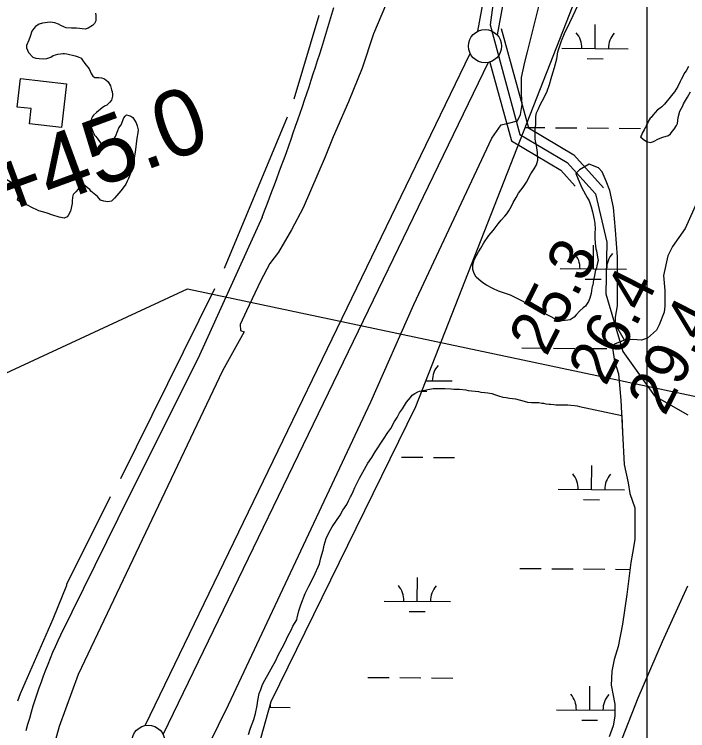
# Model space of a CAD drawing. Extents: x 3271442 to 3309282, y 752266 to 777610.
# Drawn here: x 3285122 to 3286138, y 766109 to 767190 of the extents above; entities that cross this region are included whole.
import ezdxf

# ---------------------------------------------------------------- set-up
doc = ezdxf.new("R2010")
doc.units = 0
for name, color, linetype in [('V-BLDG-OTLN', 7, 'Continuous'), ('V-GRID-MAJR', 7, 'Continuous'), ('V-LEVE-TOET', 7, 'Continuous'), ('V-RIVR-RANG', 7, 'Continuous'), ('V-ROAD-CNTR', 7, 'Continuous'), ('V-SITE-VEGE', 7, 'Continuous'), ('V-SURV-IDEN', 7, 'Continuous'), ('V-SURV-LINE', 7, 'Continuous'), ('V-TOPO-MINR', 7, 'Continuous'), ('V-TOPO-SHOR', 7, 'Continuous'), ('V-UTIL-LINE', 7, 'Continuous'), ('V-WETL-SWMP', 7, 'Continuous')]:
    doc.layers.add(name, color=color, linetype=linetype)

msp = doc.modelspace()

# ---------------------------------------------------------------- linework, layer by layer
at = {"layer": 'V-BLDG-OTLN'}
msp.add_lwpolyline([(3285145, 767024.6), (3285147.7, 767047.6), (3285126.6, 767050), (3285131.6, 767093.1), (3285200.8, 767085.1), (3285193.2, 767019)], close=True, dxfattribs=at)
at = {"layer": 'V-GRID-MAJR'}
msp.add_spline([(3286078, 757644.7), (3286077.1, 763703.6), (3286076.2, 769765.5), (3286075.4, 775827.4), (3286075.4, 775830.5)], degree=3, dxfattribs=at)
at = {"layer": 'V-LEVE-TOET'}
for points in [[(3285399.7, 766055.2), (3285445, 766148.2), (3285660, 766605.4), (3285724.8, 766752.3), (3285842.3, 767003), (3285856.6, 767022.9), (3285867.4, 767025.7), (3285881.1, 767029), (3285885.6, 767038.7), (3285888, 767054), (3285886.9, 767069.9), (3285887, 767094.4), (3285892.2, 767117.6), (3285896.3, 767133.5), (3285919.4, 767226.1), (3286015.1, 767705.3), (3286090.6, 768109.6), (3286175.4, 768562.2), (3286231.2, 768857.5), (3286256.7, 768984.7), (3286280.4, 769073.9), (3286345.1, 769332.2)], [(3285696.1, 767236.6), (3285663.9, 767160.6), (3285646.7, 767108.4), (3285626, 767057.9), (3285603.1, 767005.2), (3285591, 766975.1), (3285557.7, 766897.9), (3285540, 766864.5), (3285520.5, 766831), (3285507.4, 766814), (3285493.6, 766787.4), (3285472.4, 766742.6), (3285462.7, 766722.1), (3285463.2, 766713.1), (3285468.9, 766710.8), (3285436.2, 766651.8), (3285218.4, 766194.1), (3285189.7, 766115.7), (3285173.5, 766055.6)]]:
    msp.add_lwpolyline(points, dxfattribs=at)
at = {"layer": 'V-ROAD-CNTR'}
for points in [[(3285692, 767487.4), (3285764.1, 767481.4), (3285854.2, 767284.3), (3285839.6, 767174.2), (3285884.7, 767008.7), (3285956.1, 766966.3), (3285998.6, 766919), (3286015.9, 766846.1), (3286014.2, 766768.2), (3286039.7, 766681.3), (3286087.8, 766614.1), (3286138, 766585.7)], [(3285856.6, 767168.7), (3285897.6, 767018.5), (3285965.8, 766978.1), (3286010.7, 766927.9)], [(3285839, 767119.2), (3285871.8, 766998.8), (3285946.5, 766954.6), (3285968.2, 766930.5)], [(3285495.8, 766883.7), (3285401.4, 766675.5), (3285278.5, 766428.7), (3285191.7, 766253.2)]]:
    msp.add_lwpolyline(points, dxfattribs=at)
for centre, radius, start, end in [((3281662.7, 768375), 4113, 338.7423, 343.4002), ((3285957.6, 765895.8), 845.1, 154.9809, 165.3761)]:
    msp.add_arc(centre, radius, start, end, dxfattribs=at)
at = {"layer": 'V-SITE-VEGE'}
for p, q in [((3285730.5, 766620.1), (3285733.4, 766621.1)), ((3285733.4, 766621.1), (3285741.2, 766623)), ((3285741.2, 766623), (3285745.6, 766624)), ((3285745.6, 766624), (3285753.9, 766625.4)), ((3285753.9, 766625.4), (3285771.4, 766625.3)), ((3285771.4, 766625.3), (3285781.1, 766624.8)), ((3285781.1, 766624.8), (3285785, 766624.3)), ((3285785, 766624.3), (3285785.7, 766624.3)), ((3285785.7, 766624.3), (3285793.8, 766624.3)), ((3285793.8, 766624.3), (3285803.1, 766623.2)), ((3285803.1, 766623.2), (3285806.5, 766622.2)), ((3285806.5, 766622.2), (3285822, 766620.7)), ((3285822, 766620.7), (3285825.9, 766619.7)), ((3285713.8, 766604.6), (3285719.7, 766611.9)), ((3285719.7, 766611.9), (3285722.2, 766615.3)), ((3285722.2, 766615.3), (3285726.1, 766617.7)), ((3285726.1, 766617.7), (3285730.5, 766620.1)), ((3285825.9, 766619.7), (3285831.8, 766619.2)), ((3285831.8, 766619.2), (3285836.2, 766618.7)), ((3285836.2, 766618.7), (3285842.5, 766617.7)), ((3285842.5, 766617.7), (3285846.4, 766616.2)), ((3285846.4, 766616.2), (3285852.2, 766614.3)), ((3285852.2, 766614.3), (3285859, 766612.3)), ((3285859, 766612.3), (3285863.9, 766611.8)), ((3285863.9, 766611.8), (3285868.8, 766610.8)), ((3285868.8, 766610.8), (3285878, 766609.8)), ((3285878, 766609.8), (3285891.2, 766606.3)), ((3285707.5, 766594.9), (3285713.8, 766604.6)), ((3285891.2, 766606.3), (3285896, 766604.8)), ((3285896, 766604.8), (3285901.9, 766604.3)), ((3285901.9, 766604.3), (3285913.1, 766604.3)), ((3285913.1, 766604.3), (3285917.5, 766603.3)), ((3285917.5, 766603.3), (3285920.4, 766603.3)), ((3285920.4, 766603.3), (3285923.8, 766602.3)), ((3285923.8, 766602.3), (3285928.7, 766601.8)), ((3285928.7, 766601.8), (3285931.1, 766601.8)), ((3285931.1, 766601.8), (3285936, 766601.3)), ((3285936, 766601.3), (3285938.9, 766600.8)), ((3285938.9, 766600.8), (3285949.6, 766600.7)), ((3285949.6, 766600.7), (3285956.9, 766600.7)), ((3285956.9, 766600.7), (3285961.3, 766600.2)), ((3285961.3, 766600.2), (3285967.1, 766599.7)), ((3285967.1, 766599.7), (3285971, 766599.2)), ((3285971, 766599.2), (3285974.4, 766598.2)), ((3285699.6, 766581.8), (3285703, 766588.6)), ((3285703, 766588.6), (3285707.5, 766594.9)), ((3285974.4, 766598.2), (3286038.2, 766584.6)), ((3285695.7, 766575.4), (3285699.6, 766581.8)), ((3286038.2, 766584.6), (3286039.6, 766559.1)), ((3285689.8, 766564.8), (3285695.7, 766575.4)), ((3285679, 766548.7), (3285685.4, 766558.9)), ((3285685.4, 766558.9), (3285689.8, 766564.8)), ((3286039.6, 766559.1), (3286041.7, 766510.7)), ((3285666.3, 766529.8), (3285679, 766548.7)), ((3285661.4, 766521.5), (3285666.3, 766529.8)), ((3285642.7, 766489.9), (3285655.5, 766512.8)), ((3285655.5, 766512.8), (3285661.4, 766521.5)), ((3286041.7, 766510.7), (3286047.8, 766482.9)), ((3285635.8, 766475.8), (3285642.7, 766489.9)), ((3286047.8, 766482.9), (3286050.6, 766466.9)), ((3285630.4, 766463.7), (3285633.4, 766470)), ((3285633.4, 766470), (3285635.8, 766475.8)), ((3285626, 766455.9), (3285629.4, 766461.7)), ((3285629.4, 766461.7), (3285630.4, 766463.7)), ((3286050.6, 766466.9), (3286057.9, 766445.3)), ((3285617.7, 766441.8), (3285623.6, 766450.5)), ((3285623.6, 766450.5), (3285626, 766455.9)), ((3285613.7, 766434.5), (3285617.7, 766441.8)), ((3286057.9, 766445.3), (3286058.2, 766397.6)), ((3285601.5, 766416.5), (3285613.7, 766434.5)), ((3285597.1, 766408.8), (3285601.5, 766416.5)), ((3285592.7, 766399), (3285597.1, 766408.8)), ((3285589.7, 766388.8), (3285592.7, 766399)), ((3286058.2, 766397.6), (3286054.2, 766377.1)), ((3285588.2, 766381.5), (3285589.7, 766388.8)), ((3285584.7, 766369.8), (3285588.2, 766381.5)), ((3286054.2, 766377.1), (3286051.9, 766362.9)), ((3285573.9, 766341.6), (3285582.3, 766361.1)), ((3285582.3, 766361.1), (3285584.7, 766369.8)), ((3286051.9, 766362.9), (3286046, 766314.7)), ((3285566.5, 766327), (3285573.9, 766341.6)), ((3285560.7, 766315.9), (3285566.5, 766327)), ((3285554.2, 766298.8), (3285560.7, 766315.9)), ((3286046, 766314.7), (3286039.5, 766269.8)), ((3285551.3, 766290.1), (3285554.2, 766298.8)), ((3285548.8, 766279.4), (3285551.3, 766290.1)), ((3285544.9, 766271.1), (3285548.3, 766276.4)), ((3285548.3, 766276.4), (3285548.8, 766279.4)), ((3285539.5, 766260.9), (3285542.4, 766266.7)), ((3285542.4, 766266.7), (3285544.9, 766271.1)), ((3286039.5, 766269.8), (3286032.6, 766236.3)), ((3285535.1, 766252.6), (3285539.5, 766260.9)), ((3285530.1, 766241.9), (3285535.1, 766252.6)), ((3285520.3, 766223), (3285526.2, 766234.1)), ((3285526.2, 766234.1), (3285530.1, 766241.9)), ((3286032.6, 766236.3), (3286026.8, 766216.4)), ((3285516.4, 766215.2), (3285520.3, 766223)), ((3285500.2, 766185.5), (3285516.4, 766215.2)), ((3286026.8, 766216.4), (3286023.3, 766198.8)), ((3286023.3, 766198.8), (3286022.1, 766177.8)), ((3285493.8, 766171.4), (3285496.3, 766178.7)), ((3285496.3, 766178.7), (3285500.2, 766185.5)), ((3286022.1, 766177.8), (3286027.7, 766149.4)), ((3285491.3, 766165.1), (3285493.8, 766171.4)), ((3285489.4, 766154.9), (3285491.3, 766165.1)), ((3285485.9, 766134.9), (3285488.4, 766147.1)), ((3285488.4, 766147.1), (3285489.4, 766154.9)), ((3286027.7, 766149.4), (3286027.6, 766131.2)), ((3285483.4, 766126.2), (3285485.9, 766134.9)), ((3285478.5, 766113), (3285483.4, 766126.2)), ((3286027.6, 766131.2), (3286025.3, 766116.4)), ((3285475.5, 766103.3), (3285478.5, 766113)), ((3286025.3, 766116.4), (3286019.5, 766100))]:
    msp.add_line(p, q, dxfattribs=at)
for points in [[(3285947.4, 767149.9), (3285951.8, 767161.1), (3285960.1, 767177.6), (3285965.1, 767187.9), (3285971.5, 767202.4), (3285974.4, 767212.2), (3285977.9, 767222.4), (3286003.1, 767285.8), (3286025.9, 767399.8), (3286045.8, 767499.5), (3286099.9, 767747.4), (3286114.2, 767912.6), (3286140.1, 768054.3)], [(3285244.6, 767191.6), (3285245.1, 767188.2), (3285245.1, 767179.9), (3285243.1, 767176), (3285240.2, 767173.1), (3285233.8, 767168.8), (3285229, 767167.3), (3285215.8, 767168.8), (3285208.5, 767168.9), (3285200.7, 767169.4), (3285197.8, 767170.4), (3285192.4, 767172.8), (3285189, 767174.8), (3285183.2, 767177.2), (3285179.8, 767177.7), (3285176.4, 767177.8), (3285164.7, 767176.3), (3285159.8, 767174.9), (3285157.4, 767173.5), (3285154.4, 767171.5), (3285151.5, 767168.6), (3285148.6, 767164.2), (3285146.1, 767156.4), (3285144.1, 767151.1)], [(3285144.1, 767151.1), (3285140.7, 767142.8), (3285140.7, 767139.4), (3285143.6, 767132.1), (3285150.3, 767125.2), (3285154.7, 767123.8), (3285159.6, 767123.3), (3285166.9, 767122.7), (3285171.3, 767123.2), (3285177.1, 767125.1), (3285181, 767127.6), (3285187.9, 767129.5), (3285191.8, 767130.4), (3285195.2, 767130.9), (3285198.1, 767130.9), (3285201.5, 767130.4), (3285214.2, 767127.4), (3285218.6, 767125.9), (3285222.9, 767123.5), (3285224.9, 767120.6), (3285228.7, 767115.7), (3285235, 767107.4), (3285238.4, 767100.5), (3285240.8, 767096.6), (3285243.8, 767094.7), (3285249.6, 767094.6), (3285253.5, 767094.1), (3285257.4, 767093.1), (3285260.3, 767091.2), (3285263.7, 767087.8), (3285267.1, 767081.9), (3285269, 767076), (3285270, 767073.6), (3285270.4, 767068.7), (3285270.4, 767066.3), (3285269, 767060.5), (3285266.5, 767057.1), (3285261.6, 767052.7), (3285258.2, 767051.2), (3285254.8, 767048.8), (3285246, 767041.6), (3285241.6, 767037.7), (3285240.1, 767035.7), (3285238.6, 767032.8), (3285238.1, 767030.4), (3285238.1, 767020.2), (3285240.5, 767013.3), (3285242, 767009.9), (3285243.4, 767007.5)], [(3286003.1, 766958.1), (3285988.9, 766963.8), (3285974.6, 766955.3), (3285968.9, 766949.6), (3285977.6, 766929.1), (3285983.4, 766918.2), (3285985.9, 766913.5), (3285989.2, 766908.6), (3285992.1, 766899.3), (3285994.1, 766892), (3285996.4, 766880.3), (3285997.4, 766874.5), (3285998.3, 766866.2), (3285997.8, 766860.3), (3285997.8, 766852.1), (3285998.2, 766844.8), (3285999.2, 766836), (3286000.1, 766833.1), (3286001.6, 766823.3), (3286002.5, 766818.4), (3286001.5, 766815), (3286000.5, 766810.6), (3286000, 766807.2), (3285998.1, 766801.9), (3285997.6, 766798.5), (3285997.1, 766796), (3285995.6, 766789.2), (3285994.6, 766781.4), (3285993.6, 766779), (3285992.6, 766773.2), (3285992.1, 766768.8), (3285990.1, 766761.5), (3285988.1, 766756.6), (3285985.2, 766752.2), (3285983.7, 766749.8), (3285983.4, 766749.5), (3285982.3, 766748.4), (3285980.3, 766746.9), (3285974.9, 766742.5), (3285969.6, 766736.7), (3285966.6, 766732.8), (3285963.7, 766730.9), (3285960.3, 766729), (3285949.5, 766727.6), (3285946.1, 766728.1), (3285938.3, 766730), (3285929.6, 766734.5), (3285917.4, 766740.8), (3285910.6, 766744.8), (3285903.4, 766749.7), (3285898, 766752.1), (3285883.4, 766759.5), (3285870.3, 766766.4), (3285852.3, 766772.3), (3285844, 766776.2), (3285834.3, 766781.1), (3285829, 766785), (3285822.6, 766789.9), (3285818.8, 766793.4), (3285815.9, 766798.7), (3285813.9, 766805.1), (3285813.5, 766811.9), (3285815.9, 766819.7), (3285822.3, 766831.3), (3285825.8, 766837.2), (3285830.2, 766845), (3285838, 766856.1), (3285844.4, 766863.9), (3285851.7, 766873.6), (3285856.6, 766879.4), (3285862, 766885.3), (3285864.9, 766889.1), (3285867.9, 766893.5), (3285871.8, 766900.3), (3285874.3, 766906.2), (3285879.2, 766913.4), (3285882.6, 766919.8), (3285889.5, 766929), (3285894.4, 766936.8), (3285901.2, 766949.4), (3285906.1, 766956.7), (3285909.6, 766963), (3285911.6, 766969.8), (3285911.1, 766981.5), (3285909.7, 766991.8), (3285907.8, 767001.5), (3285907.8, 767015.6), (3285908.9, 767023.9), (3285908.9, 767035.6), (3285909.9, 767041), (3285912.8, 767047.3), (3285915.3, 767053.1), (3285921.2, 767064.3), (3285925.6, 767074), (3285929.1, 767083.8), (3285932, 767093), (3285934.5, 767101.8), (3285937, 767109.5), (3285940.4, 767122.7), (3285941.9, 767133.4), (3285947.4, 767149.9)], [(3286138.7, 767111.2), (3286135.2, 767104.8), (3286133.3, 767101.9), (3286127.9, 767091.7), (3286126.4, 767088.3), (3286123, 767081), (3286117.6, 767072.8), (3286113.2, 767067.4), (3286102.9, 767054.3), (3286098.5, 767050.4), (3286096, 767048.5), (3286092.1, 767045.6), (3286085.3, 767037.8), (3286082.8, 767034.4), (3286081.3, 767033), (3286077.9, 767028.1), (3286076.9, 767025.2), (3286075, 767022.3), (3286074.5, 767020.3), (3286073, 767017.9), (3286072, 767015.5), (3286069.1, 767010.6), (3286068.1, 767007.7), (3286066.6, 767004.8), (3286070.5, 767001.3), (3286075.8, 766997.9), (3286081.7, 766996.4), (3286086.1, 766997.9), (3286093.9, 767002.2), (3286100.2, 767004.6), (3286108.5, 767007), (3286111.5, 767009.4), (3286114.4, 767013.3), (3286117.3, 767016.7), (3286120.8, 767022.1), (3286122.2, 767025), (3286123.3, 767034.2), (3286125.7, 767043.5), (3286128.2, 767048.4)], [(3286128.2, 767048.4), (3286130.1, 767051.8), (3286131.6, 767054.7), (3286134.6, 767060), (3286137.5, 767064.9), (3286141.9, 767072.7)], [(3285243.4, 767007.5), (3285244.9, 767006), (3285247.3, 767003.1), (3285249.2, 767000.1), (3285252.6, 766995.7), (3285255.5, 766993.8), (3285264.3, 766995.7), (3285268.2, 766997.1), (3285271.6, 767000.5), (3285272.6, 767002.5), (3285274.6, 767005.4), (3285278.5, 767014.6), (3285280, 767018.5), (3285283.4, 767022.9), (3285287.4, 767033.6), (3285289.3, 767036), (3285291.3, 767038), (3285295.2, 767037), (3285298.1, 767036), (3285301, 767034), (3285305.8, 767026.2), (3285307.3, 767021.8), (3285309.2, 767015.5), (3285308.7, 767011.1), (3285307.2, 767002.8), (3285304.7, 766981.9), (3285303.2, 766973.6), (3285301.7, 766962.9), (3285299.7, 766955.1), (3285294.3, 766942), (3285292.3, 766938.1), (3285290.4, 766933.7), (3285286.4, 766927.9), (3285283, 766923.5), (3285277.1, 766916.7), (3285273.2, 766912.3), (3285268.8, 766908), (3285263.5, 766907), (3285257.1, 766908), (3285252.3, 766909.5), (3285247.9, 766914.9), (3285237.7, 766923.2), (3285236.2, 766925.6), (3285232.8, 766928.1), (3285228.5, 766931.5), (3285226, 766931), (3285221.2, 766927.7), (3285218.7, 766926.2), (3285214.8, 766922.3), (3285210.9, 766918), (3285209.9, 766914.1), (3285209.4, 766908.2), (3285209.4, 766904.3), (3285206.9, 766893.1), (3285203.4, 766886.3), (3285202, 766884.4), (3285197.6, 766882.4), (3285189.8, 766883.9), (3285180.6, 766886.9), (3285170.3, 766890.4), (3285159.1, 766893.3), (3285155.3, 766895.3), (3285150.9, 766897.3), (3285141.2, 766902.2), (3285137.3, 766903.2), (3285135.3, 766904.1), (3285129.5, 766908.1), (3285127.1, 766909.5), (3285128.1, 766913.9), (3285129, 766919.8), (3285128.6, 766926.1), (3285127.6, 766930), (3285125.7, 766931.5), (3285110.1, 766940.8)], [(3286153.5, 766910.4), (3286134, 766866.7), (3286114.6, 766839.5), (3286107.7, 766825.3), (3286101.4, 766795.8), (3286103, 766773), (3286103.4, 766749.7), (3286102.3, 766740.7), (3286094.8, 766721.4), (3286090.8, 766713.4), (3286077.1, 766701.5), (3286068, 766698.2), (3286054.9, 766699.4), (3286043.6, 766698.8), (3286042.3, 766698.3), (3286028.7, 766721.7), (3286028.7, 766733.1), (3286031.6, 766750.1), (3286031.6, 766778.6), (3286031.6, 766824.2), (3286028.7, 766864.1), (3286025.9, 766898.3), (3286020.2, 766923.9), (3286014.5, 766938.2), (3286008.8, 766952.4), (3286003.1, 766958.1)]]:
    msp.add_lwpolyline(points, dxfattribs=at)
at = {"layer": 'V-SURV-LINE'}
for points in [[(3285821, 767164.3), (3286160.4, 769007.4)], [(3286189.9, 769002), (3285850.5, 767158.9)], [(3285319.5, 766116.9), (3285809.9, 767130.5)], [(3285836.9, 767117.4), (3285346.5, 766103.9)]]:
    msp.add_lwpolyline(points, dxfattribs=at)
for centre in [(3285832.1, 767141.9), (3285324.3, 766092.4)]:
    msp.add_circle(centre, 25, dxfattribs=at)
at = {"layer": 'V-TOPO-MINR'}
msp.add_lwpolyline([(3286137.6, 766327.3), (3286099.2, 766243.1), (3286062.7, 766158.1), (3286028.9, 766072)], dxfattribs=at)
at = {"layer": 'V-TOPO-SHOR'}
for p, q in [((3285581.5, 767188), (3285544, 767062)), ((3285533.9, 767034.6), (3285438.5, 766806.2)), ((3285424.3, 766775.7), (3285282.4, 766489.2))]:
    msp.add_line(p, q, dxfattribs=at)
for points in [[(3286153.5, 766910.4), (3286134, 766866.7), (3286114.6, 766839.5), (3286107.7, 766825.3), (3286101.4, 766795.8), (3286103, 766773), (3286103.4, 766749.7), (3286102.3, 766740.7), (3286094.8, 766721.4), (3286090.8, 766713.4), (3286077.1, 766701.5), (3286068, 766698.2), (3286054.9, 766699.4), (3286043.6, 766698.8), (3286027.1, 766692.1), (3286024.2, 766686.4), (3286027.5, 766666.5), (3286033.1, 766647.7), (3286036.9, 766607.9), (3286039.6, 766559.1), (3286041.7, 766510.7), (3286047.8, 766482.9), (3286050.6, 766466.9), (3286057.9, 766445.3), (3286058.2, 766397.6)], [(3285266.8, 766462.1), (3285201.2, 766329.9), (3285201, 766328.2), (3285180.2, 766277.6), (3285131.3, 766165), (3285127.1, 766153.7)], [(3286058.2, 766397.6), (3286054.2, 766377.1), (3286051.9, 766362.9), (3286046, 766314.7), (3286039.5, 766269.8), (3286032.6, 766236.3), (3286026.8, 766216.4), (3286023.3, 766198.8), (3286022.1, 766177.8), (3286027.7, 766149.4), (3286027.6, 766131.2), (3286025.3, 766116.4), (3286019.5, 766100)]]:
    msp.add_lwpolyline(points, dxfattribs=at)
at = {"layer": 'V-UTIL-LINE'}
msp.add_lwpolyline([(3276068, 762951.9), (3276378.3, 762949.9), (3278272.8, 763521.6), (3279552.2, 763863.5), (3279814.2, 764129.2), (3280573.5, 764542.5), (3285383.4, 766775.8), (3286916.8, 766451)], dxfattribs=at)
at = {"layer": 'V-WETL-SWMP'}
for p, q in [((3285727.5, 766598.4), (3286020.9, 767346.9)), ((3285998.1, 767138.4), (3285998.4, 767174.4)), ((3285948.1, 767138.8), (3286048.1, 767138)), ((3285986, 767123.1), (3286010, 767122.9)), ((3285892.4, 767019.2), (3285922.3, 767019)), ((3285938.3, 767018.8), (3285970.3, 767018.6)), ((3285986.3, 767018.4), (3286018.3, 767018.2)), ((3286034.3, 767018), (3286066.3, 767017.8)), ((3286153.5, 766910.4), (3286134, 766866.7)), ((3286134, 766866.7), (3286114.6, 766839.5)), ((3285995.4, 766805.7), (3285995.7, 766841.7)), ((3286114.6, 766839.5), (3286107.7, 766825.3)), ((3286107.7, 766825.3), (3286101.4, 766795.8)), ((3285945.4, 766806.2), (3286045.4, 766805.3)), ((3286101.4, 766795.8), (3286103, 766773)), ((3285983.2, 766790.4), (3286007.2, 766790.2)), ((3286103, 766773), (3286103.4, 766749.7)), ((3286102.3, 766740.7), (3286094.8, 766721.4)), ((3286103.4, 766749.7), (3286102.3, 766740.7)), ((3286094.8, 766721.4), (3286090.8, 766713.4)), ((3286090.8, 766713.4), (3286077.1, 766701.5)), ((3286043.6, 766698.8), (3286027.1, 766692.1)), ((3286054.9, 766699.4), (3286043.6, 766698.8)), ((3286068, 766698.2), (3286054.9, 766699.4)), ((3286077.1, 766701.5), (3286068, 766698.2)), ((3285887.5, 766686.6), (3285919.5, 766686.3)), ((3285935.5, 766686.2), (3285967.5, 766685.9)), ((3285983.5, 766685.8), (3286015.5, 766685.5)), ((3286027.1, 766692.1), (3286024.2, 766686.4)), ((3286024.2, 766686.4), (3286027.5, 766666.5)), ((3286027.5, 766666.5), (3286033.1, 766647.7)), ((3286033.1, 766647.7), (3286036.9, 766607.9)), ((3285742.6, 766637), (3285782.5, 766636.7)), ((3285736.6, 766621.6), (3285744.4, 766621.6)), ((3286036.9, 766607.9), (3286039.6, 766559.1)), ((3285509.7, 766153.1), (3285727.5, 766598.4)), ((3286039.6, 766559.1), (3286041.7, 766510.7)), ((3285690.1, 766522), (3285690.2, 766522)), ((3285706.2, 766521.9), (3285738.2, 766521.6)), ((3285754.2, 766521.5), (3285786.2, 766521.2)), ((3285992.6, 766473.1), (3285992.9, 766509.1)), ((3286041.7, 766510.7), (3286047.8, 766482.9)), ((3286047.8, 766482.9), (3286050.6, 766466.9)), ((3285942.6, 766473.5), (3286042.6, 766472.7)), ((3286050.6, 766466.9), (3286057.9, 766445.3)), ((3285980.5, 766457.7), (3286004.5, 766457.5)), ((3286057.9, 766445.3), (3286058.2, 766397.6)), ((3286058.2, 766397.6), (3286054.2, 766377.1)), ((3286054.2, 766377.1), (3286051.9, 766362.9)), ((3286051.9, 766362.9), (3286046, 766314.7)), ((3285884.8, 766353.9), (3285916.8, 766353.6)), ((3285932.8, 766353.5), (3285964.8, 766353.2)), ((3285980.8, 766353.1), (3286012.8, 766352.8)), ((3286028.8, 766352.7), (3286050.6, 766352.5)), ((3285729.8, 766304.4), (3285730.1, 766340.4)), ((3286046, 766314.7), (3286039.5, 766269.8)), ((3285679.8, 766304.8), (3285779.8, 766304)), ((3285717.7, 766289.1), (3285741.7, 766288.9)), ((3286039.5, 766269.8), (3286032.6, 766236.3)), ((3286032.6, 766236.3), (3286026.8, 766216.4)), ((3286026.8, 766216.4), (3286023.3, 766198.8)), ((3285655.4, 766189.6), (3285687.4, 766189.3)), ((3285703.4, 766189.2), (3285735.4, 766188.9)), ((3285751.4, 766188.8), (3285783.4, 766188.5)), ((3286023.3, 766198.8), (3286022.1, 766177.8)), ((3286022.1, 766177.8), (3286027.7, 766149.4)), ((3285989.9, 766140.4), (3285990.2, 766176.4)), ((3285396.2, 765755.2), (3285509.7, 766153.1)), ((3286027.7, 766149.4), (3286027.6, 766131.2)), ((3285507.2, 766144.4), (3285538, 766144.1)), ((3285939.9, 766140.8), (3286027.6, 766140.1)), ((3285977.8, 766125.1), (3286001.8, 766124.9)), ((3286027.6, 766131.2), (3286025.3, 766116.4)), ((3286025.3, 766116.4), (3286019.5, 766100))]:
    msp.add_line(p, q, dxfattribs=at)
for centre, start, end in [((3285942.9, 767139.3), 358.7563, 40.2999), ((3286053.3, 767138.4), 138.7563, 180.2999), ((3285940.1, 766806.7), 358.7563, 40.2999), ((3286050.6, 766805.8), 138.7563, 180.2999), ((3285787.8, 766637.1), 138.7563, 180.2999), ((3285937.4, 766474), 358.7563, 40.2999), ((3286047.9, 766473.1), 138.7563, 180.2999), ((3285674.5, 766305.4), 358.7563, 40.2999), ((3285785, 766304.4), 138.7563, 180.2999), ((3285934.6, 766141.3), 358.7563, 40.2999), ((3286045.1, 766140.4), 138.7563, 180.2999), ((3285543.2, 766144.6), 175.3883, 180.2999)]:
    msp.add_arc(centre, 35.2, start, end, dxfattribs=at)

# ---------------------------------------------------------------- texts
at = {"layer": 'V-RIVR-RANG'}
for s, p in [('25.3', (3285924.6, 766672.2)), ('26.4', (3286013.9, 766627.3)), ('29.4', (3286103.2, 766582.3))]:
    msp.add_text(s, height=67, rotation=63.1183, dxfattribs=at).set_placement(p)
at = {"layer": 'V-SURV-IDEN'}
msp.add_text('2774+45.0', height=100, rotation=20.1533, dxfattribs=at).set_placement((3284825.8, 766772.9))

doc.saveas('drawing.dxf')
